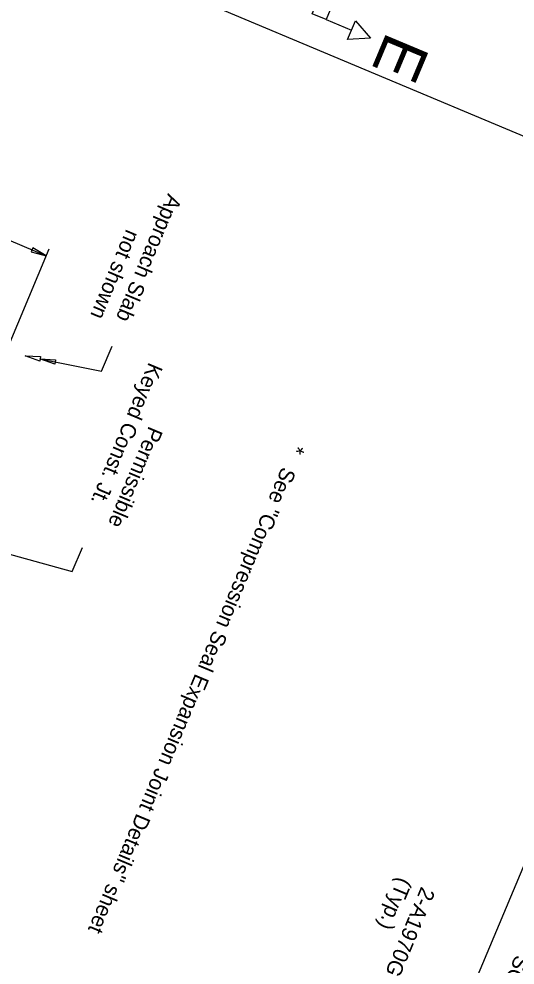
# Model space of a CAD drawing. Extents: x 1968564 to 1968711, y 796599 to 796794.
# Drawn here: x 1968645.19 to 1968661.26, y 796684.77 to 796715.41 of the extents above; entities that cross this region are included whole.
import ezdxf

# ---------------------------------------------------------------- set-up
doc = ezdxf.new("R2010")
doc.units = 0
for name, color, linetype in [('BR_AUTO DIMENSION', 7, 'Continuous'), ('BR_TABLE LINES', 7, 'Continuous'), ('BR_TEXT', 7, 'Continuous')]:
    doc.layers.add(name, color=color, linetype=linetype)

msp = doc.modelspace()

# ---------------------------------------------------------------- linework, layer by layer
at = {"layer": 'BR_AUTO DIMENSION'}
for p, q in [((1968624.948, 796726.966), (1968669, 796708.489)), ((1968642.39, 796709.282), (1968646.079, 796707.735)), ((1968643.179, 796700.82), (1968646.176, 796707.965)), ((1968647.87, 796703.997), (1968648.211, 796704.81)), ((1968645.877, 796704.395), (1968647.87, 796703.997)), ((1968637.896, 796700.002), (1968646.922, 796697.508)), ((1968646.922, 796697.508), (1968647.249, 796698.288)), ((1968664.941, 796696.102), (1968658.562, 796680.894))]:
    msp.add_line(p, q, dxfattribs=at)
for points in [[(1968645.589, 796707.859), (1968646.079, 796707.735), (1968645.647, 796707.997)], [(1968645.868, 796704.325), (1968645.393, 796704.496), (1968645.898, 796704.472)], [(1968646.353, 796704.223), (1968645.877, 796704.395), (1968646.382, 796704.37)]]:
    msp.add_lwpolyline(points, close=True, dxfattribs=at)
at = {"layer": 'BR_TABLE LINES'}
msp.add_line((1968655.142, 796715.386), (1968655.961, 796715.042), dxfattribs=at)
for points in [[(1968655.206, 796716.804), (1968655.657, 796716.615), (1968655.142, 796715.386), (1968654.691, 796715.575)], [(1968656.09, 796715.349), (1968656.576, 796714.784), (1968655.832, 796714.735)]]:
    msp.add_lwpolyline(points, close=True, dxfattribs=at)

# ---------------------------------------------------------------- texts
at = {"layer": 'BR_TEXT'}
for s, height, p in [('E', 1.5, (1968657.126, 796715.033)), ('Approach Slab', 0.49995, (1968650.024, 796709.77)), ('not shown', 0.4999, (1968648.675, 796708.621)), ('Keyed Const. Jt.', 0.49995, (1968649.408, 796704.31)), ('Permissible', 0.49995, (1968649.409, 796702.243)), ('*', 0.5, (1968654.013, 796701.681)), ('See "Compression Seal Expansion Joint Details" sheet', 0.50013, (1968653.718, 796700.927)), ('(Typ.)', 0.4999, (1968657.488, 796687.639)), ('2-A1970G', 0.4999, (1968658.227, 796687.329)), ('SC1370G', 0.4999, (1968661.283, 796685.119))]:
    msp.add_text(s, height=height, rotation=247.246, dxfattribs=at).set_placement(p)

doc.saveas('drawing.dxf')
